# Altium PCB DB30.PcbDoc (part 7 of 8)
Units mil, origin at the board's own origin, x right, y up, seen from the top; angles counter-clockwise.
Board outline 3236.22 x 4456.69 mil, 8 copper layers (Top Layer, MidLayer1, MidLayer2, GND-Layer5, MidLayer3, VCC, MidLayer4, Bottom Layer), stack 61.8 mil thick; 219 components, 472 nets, 1811 pads, 1561 vias.
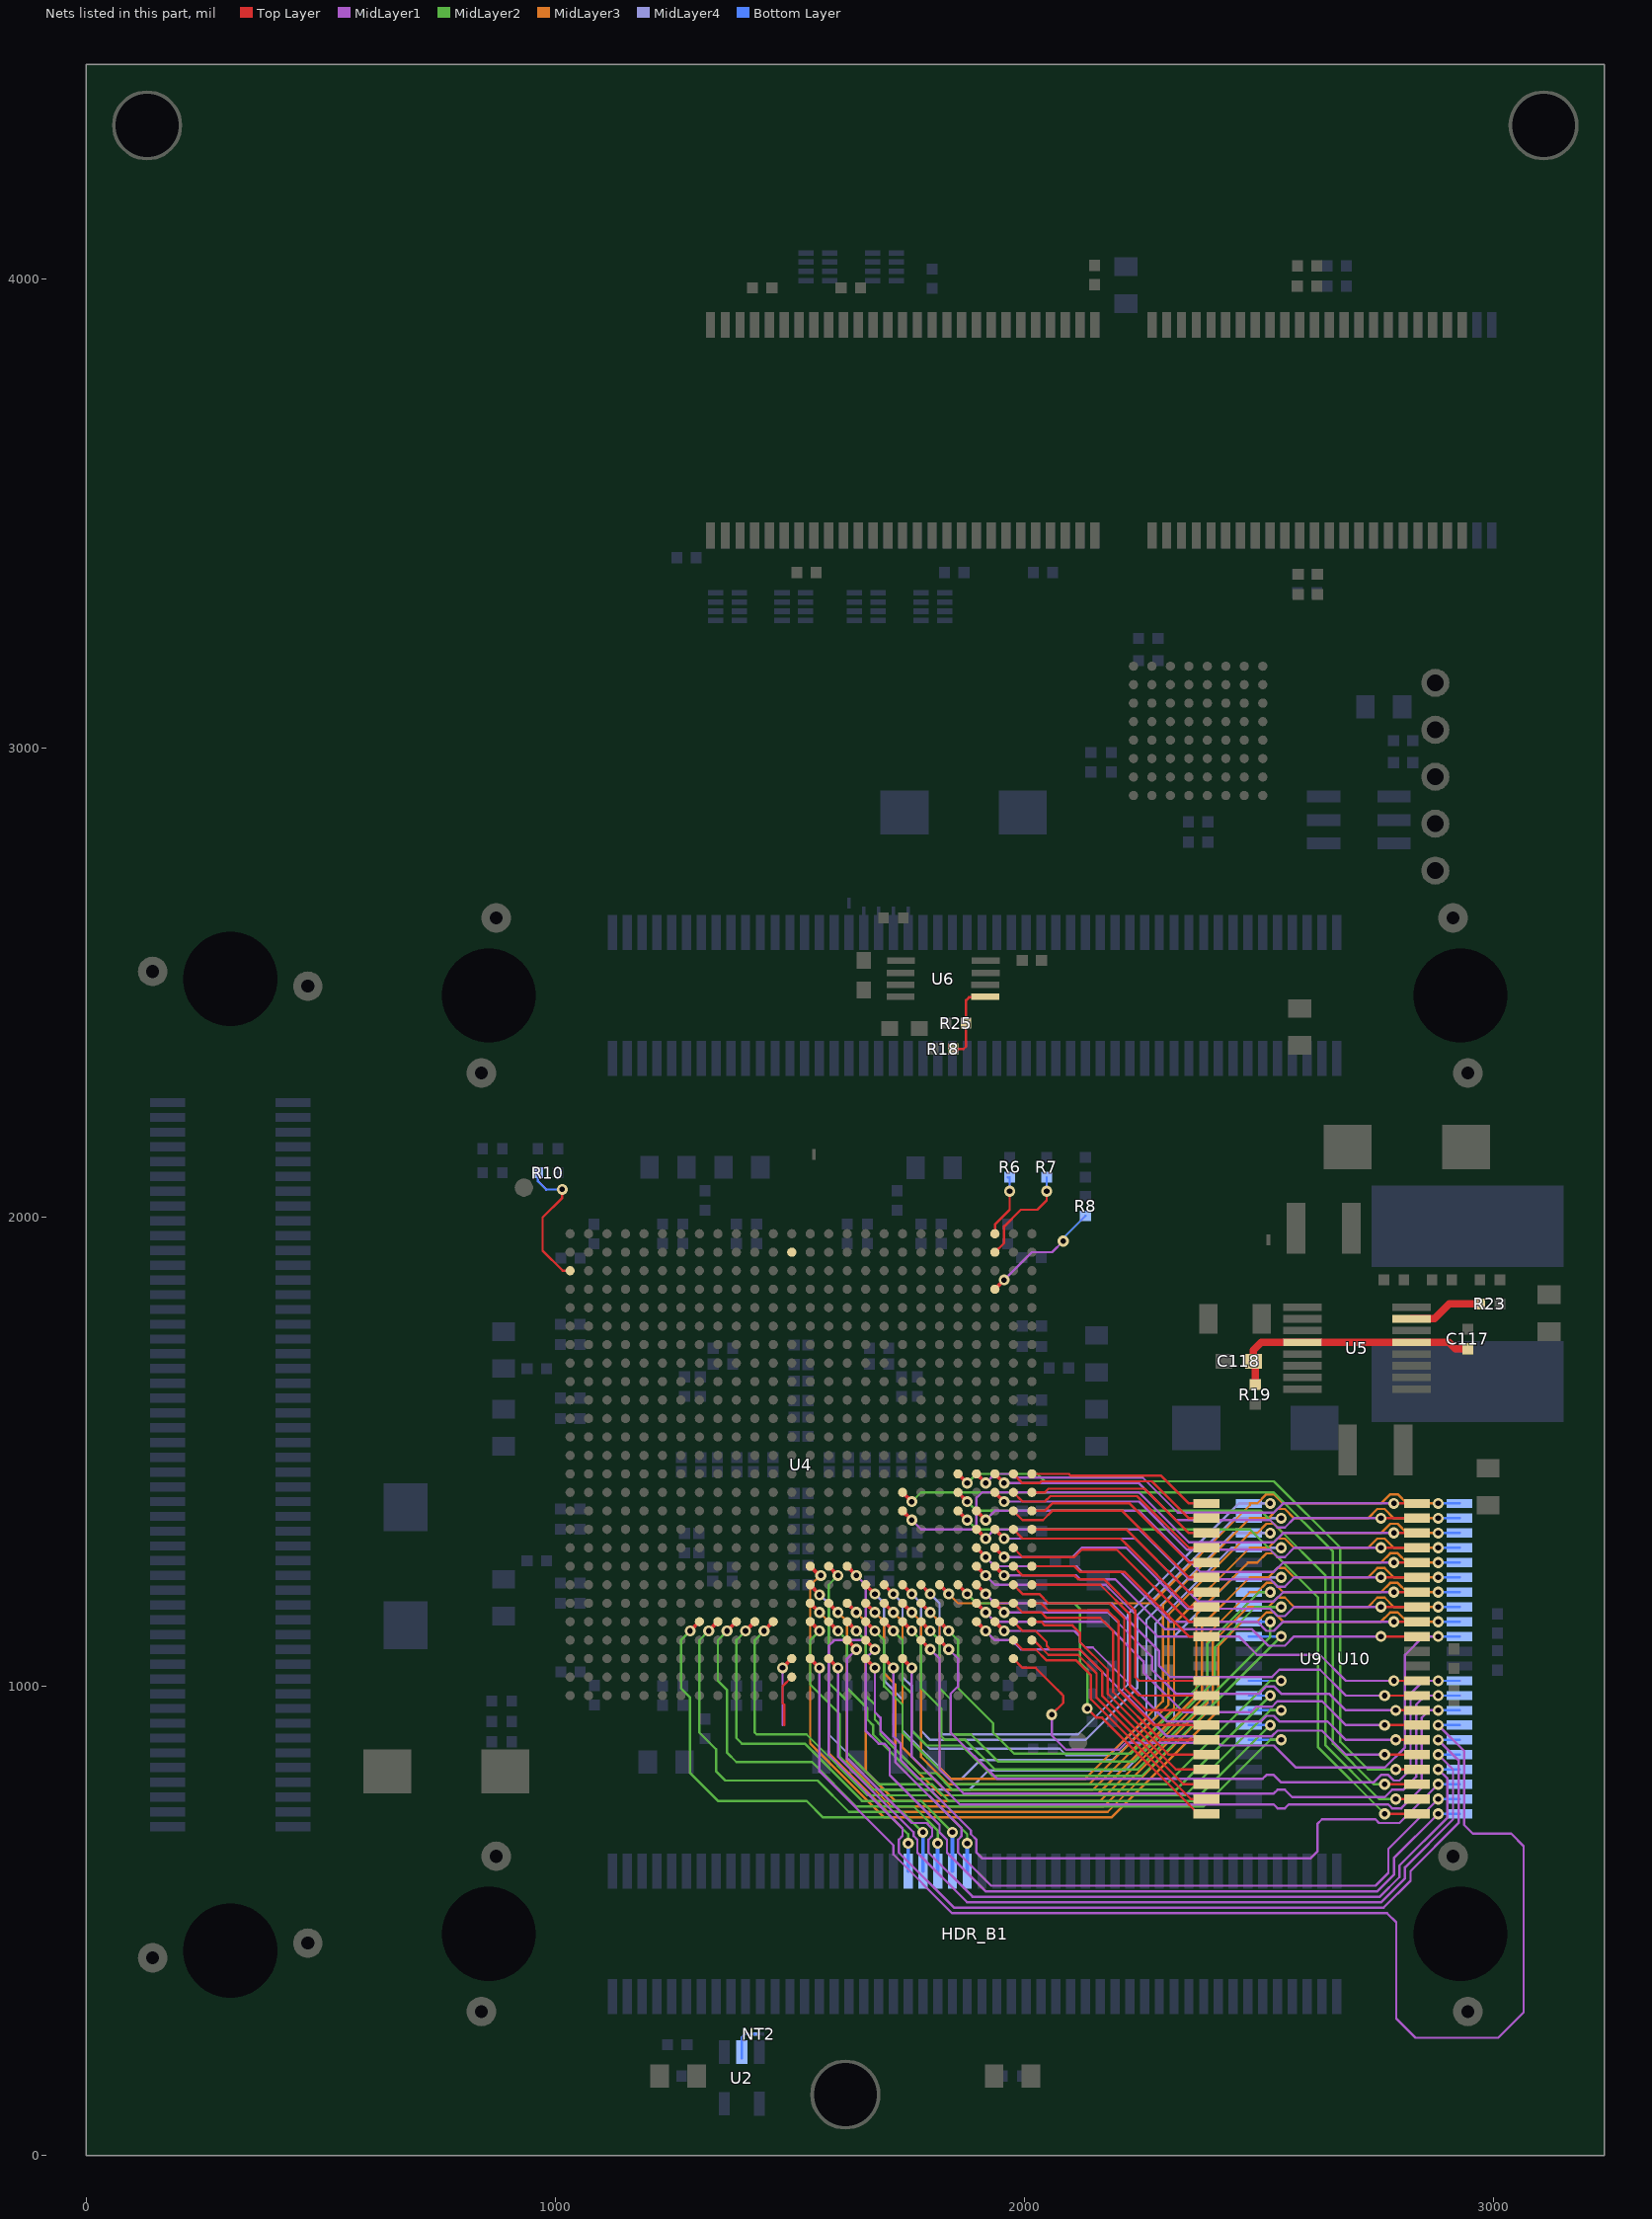
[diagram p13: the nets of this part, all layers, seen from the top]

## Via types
v1: diameter 23.62, hole 11.81, Top Layer to Bottom Layer, 944 vias
v2: diameter 23.62, hole 11.81, Top Layer to Bottom Layer, tented both sides, 477 vias
v3: diameter 27.56, hole 15.75, Top Layer to Bottom Layer, 139 vias
v4: diameter 23.62, hole 11.81, Top Layer to Bottom Layer, tented top, 1 vias

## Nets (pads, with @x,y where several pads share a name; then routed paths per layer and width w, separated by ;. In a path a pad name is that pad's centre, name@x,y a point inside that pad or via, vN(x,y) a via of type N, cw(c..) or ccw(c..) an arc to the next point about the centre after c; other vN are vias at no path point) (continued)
SRAM1_A6: U4.Y17 U10.19 | length 1586.2
  Top Layer w7.87: U4.Y17@1661.42,1216.54 v1(1681.1,1196.85)
  MidLayer4 w5: v1(1681.1,1196.85) 1700.79,1177.16 1700.79,1011.81 1740.16,972.44 1740.16,917.32 1740.16,905.51 1842.52,803.15 1866.14,803.15 1905.51,842.52 2187.01,842.52 2279.53,935.04 2279.53,1133.86 2440.94,1295.28 v1(2547.24,1295.28)
  Bottom Layer w5: U10.19@2478.44,1295.27 v1(2547.24,1295.28) v1@2551.18,1295.28
SRAM1_A7: U4.Y18 U10.20 | length 1489.3
  Top Layer w7.87: U4.Y18@1700.79,1216.54 v1(1720.47,1196.85)
  MidLayer4 w5: v1(1720.47,1196.85) 1740.16,1177.16 1740.16,1019.69 1759.84,1000 1759.84,917.32 1759.84,905.51 1798.23,867.13 2075.05,867.13 2088.83,853.35 2181.1,853.35 2259.84,932.09 2259.84,1141.73 2444.88,1326.77 2456.69,1326.77 v1(2523.83,1326.76)
  Bottom Layer w5: U10.20@2478.44,1326.76 v1@2527.77,1326.76
SRAM1_A8: U4.Y19 U10.21 | length 1468.5
  Top Layer w7.87: U4.Y19@1740.16,1216.54 v1(1759.84,1196.85)
  MidLayer4 w5: v1(1759.84,1196.85) 1779.53,1177.16 1779.53,917.32 1779.53,905.51 1799.21,885.83 2129.92,885.83 2240.16,996.06 2240.16,1151.21 2447.21,1358.27 v1(2547.24,1358.27)
  Bottom Layer w5: U10.21@2472.44,1358.27 U10.21@2478.44,1358.26 v1(2547.24,1358.27) v1@2551.18,1358.27
SRAM1_A9: U4.Y20 U10.22 | length 1372.4
  Top Layer w7.87: U4.Y20@1779.53,1216.54 v1(1799.21,1196.85)
  MidLayer4 w5: v1(1799.21,1196.85) 1818.9,1177.16 1818.9,917.32 1818.9,905.51 1826.77,897.64 2114.17,897.64 2220.47,1003.94 2220.47,1153.54 2456.68,1389.75 v1(2523.83,1389.75)
  Bottom Layer w5: U10.22@2478.44,1389.75 v1(2523.83,1389.75)
SRAM1_A10: U4.Y21 U10.23 | length 1247.9
  Top Layer w7.87: U4.Y21@1818.9,1216.54 v1(1838.58,1196.85)
  MidLayer3 w5: v1(1838.58,1196.85) 1858.27,1177.16 2078.74,1177.17 2094.49,1177.17 2271.65,1177.17 2480.33,1385.84 2480.33,1389.75 2496.27,1389.75 2515.96,1409.44 2531.7,1409.44 2551.38,1389.76 ; 2551.18,1389.76 2551.38,1389.76 ; v1(2881.9,1389.75) 2814.97,1389.75 2795.28,1409.45 2779.53,1409.45 2759.84,1389.76 2551.38,1389.76
  Bottom Layer w5: v1(2881.9,1389.75) U10.23@2927.25,1389.75
SRAM1_A11: U4.AA20 U10.24 | length 1867.3
  Top Layer w7.87: U4.AA20@1779.53,1177.17 v1(1799.21,1157.48)
  MidLayer3 w5: v1(1799.21,1157.48) 1818.9,1137.79 1818.9,917.32 1818.9,905.51 1818.9,826.77 1842.52,803.15 2129.92,803.15 2295.28,968.5 2295.28,1173.23 2480.31,1358.27 2519.69,1358.27 2539.37,1377.95 2555.12,1377.95 2574.8,1358.27 2732.28,1358.27 2751.97,1377.95 2767.72,1377.95 2787.41,1358.26 v1(2881.9,1358.26)
  Bottom Layer w5: v1(2881.9,1358.26) U10.24@2927.25,1358.26
SRAM1_A12: U4.AA19 U10.25 | length 1883.2
  Top Layer w7.87: U4.AA19@1740.16,1177.17 v1(1759.84,1157.48)
  MidLayer3 w5: v1(1759.84,1157.48) 1779.53,1137.79 1779.53,917.32 1779.53,905.51 1779.53,849.41 1837.6,791.34 2137.8,791.34 2307.09,960.63 2307.09,1153.52 2480.33,1326.76 2496.27,1326.76 2515.96,1346.45 2531.7,1346.45 2551.38,1326.77 2759.84,1326.77 2779.53,1346.46 2795.28,1346.46 2814.97,1326.76 v1(2881.9,1326.76)
  Bottom Layer w5: v1(2881.9,1326.76) U10.25@2927.25,1326.76
SRAM1_A13: U4.AA18 U10.26 | length 1900.3
  Top Layer w7.87: U4.AA18@1700.79,1177.17 v1(1720.47,1157.48)
  MidLayer3 w5: v1(1720.47,1157.48) 1740.16,1137.79 1740.16,917.32 1740.16,905.51 1740.16,870.08 1830.71,779.53 2145.67,779.53 2318.9,952.76 2318.9,1133.86 2480.31,1295.28 2519.69,1295.28 2539.37,1314.96 2555.12,1314.96 2574.8,1295.28 2732.28,1295.28 2751.97,1314.96 2767.72,1314.96 2787.41,1295.27 v1(2881.9,1295.27)
  Bottom Layer w5: v1(2881.9,1295.27) U10.26@2927.25,1295.27
SRAM1_A14: U4.AA17 U10.27 | length 1920.3
  Top Layer w7.87: U4.AA17@1661.42,1177.17 v1(1681.1,1157.48)
  MidLayer3 w5: v1(1681.1,1157.48) 1700.79,1137.79 1700.79,1027.56 1724.41,1003.94 1724.41,917.32 1724.41,905.51 1724.41,866.14 1822.83,767.72 2153.54,767.72 2366.14,980.31 2366.14,1153.54 2476.37,1263.77 2496.27,1263.77 2515.96,1283.45 2531.7,1283.45 2551.38,1263.78 2759.84,1263.78 2779.53,1283.46 2795.28,1283.46 2814.97,1263.77 v1(2881.9,1263.77)
  Bottom Layer w5: v1(2881.9,1263.77) U10.27@2927.25,1263.77
SRAM1_A15: U4.AD18 U10.42 | length 1635.8
  Top Layer w7.87: U4.AD18@1700.79,1059.05 v1(1720.47,1039.37)
  MidLayer1 w5: v1(1720.47,1039.37) 1720.47,917.32 1720.47,905.51 1720.47,893.7 1736.22,877.95 1736.22,842.52 1885.83,692.91 1885.83,685.04 1897.64,673.23 1897.64,645.67 1909.45,633.86 2610.24,633.86 2624.26,647.88 2624.26,706.94 2633.86,716.54 2748.03,716.54 2755.91,708.66 2799.21,708.66 v1(2881.9,791.33)
  Bottom Layer w5: v1(2881.9,791.33) U10.42@2927.25,791.33
SRAM1_A16: U4.AD17 U10.43 | length 1706.2
  Top Layer w7.87: U4.AD17@1661.42,1059.05 v1(1681.1,1039.37)
  MidLayer1 w5: v1(1681.1,1039.37) 1681.1,944.88 1692.91,933.07 1692.91,917.32 1692.91,905.51 1724.41,874.02 1724.41,838.58 1866.14,696.85 1866.14,681.1 1858.27,673.23 1858.27,645.67 1928.89,575.05 2748.28,575.05 2775.59,602.36 2775.59,653.54 v1(2881.9,759.83)
  Bottom Layer w5: v1(2881.9,759.83) U10.43@2927.25,759.83
SRAM1_A17: U4.AC17 U10.44 | length 1763.6
  Top Layer w7.87: U4.AC17@1661.42,1098.43 v1(1681.1,1078.74)
  MidLayer1 w5: v1(1681.1,1078.74) 1661.42,1059.05 1661.42,917.32 1661.42,905.51 1688.98,877.95 1700.79,877.95 1712.6,866.14 1712.6,811.02 1818.9,704.72 1818.9,688.98 1834.65,673.23 1834.65,645.67 1917.08,563.24 2752.21,563.24 2787.4,598.43 2787.4,633.86 v1(2881.9,728.34)
  Bottom Layer w5: v1(2881.9,728.34) U10.44@2927.25,728.34
SRAM1_A18: U4.AA16 U10.28 | length 1988.7
  Top Layer w7.87: U4.AA16@1622.05,1177.17 v1(1641.73,1157.48)
  MidLayer3 w5: v1(1641.73,1157.48) 1661.42,1137.79 1661.42,917.32 1661.42,905.51 1661.42,818.9 1724.41,755.91 2161.42,755.91 2377.95,972.44 2377.95,1129.92 2480.31,1232.28 2519.69,1232.28 2539.37,1251.97 2555.12,1251.97 2574.8,1232.28 2732.28,1232.28 2751.97,1251.97 2767.72,1251.97 2787.41,1232.28 v1(2881.9,1232.27)
  Bottom Layer w5: v1(2881.9,1232.27) U10.28@2927.25,1232.27
SRAM1_D0: U4.W15 U10.7 | length 1490.6
  Top Layer w7.87: U4.W15@1582.68,1255.91 v1(1602.36,1236.22)
  MidLayer2 w5: v1(1602.36,1236.22) 1582.68,1216.54 1582.68,1019.68 1582.68,1007.87 1622.05,968.5 1622.05,917.32 1622.05,905.51 1622.05,858.27 1688.98,791.34 1803.15,791.34 1838.58,755.91 2362.2,755.91 2523.6,917.3 v1(2523.83,917.3)
  Bottom Layer w5: U10.7@2478.44,917.31 v1(2523.83,917.3) v1@2527.77,917.3
SRAM1_D1: U4.AB15 U10.8 | length 1351
  Top Layer w7.87: U4.AB15@1582.68,1137.8 v1(1602.36,1118.11)
  MidLayer2 w5: v1(1602.36,1118.11) 1622.05,1098.42 1622.05,996.06 1665.35,952.76 1665.35,929.13 1677.17,917.32 1677.17,905.51 1677.17,897.64 1771.65,803.15 1807.09,803.15 1834.65,775.59 1842.52,767.72 2342.52,767.72 2523.62,948.82 v1(2547.24,948.82)
  Bottom Layer w5: U10.8@2478.44,948.81 v1(2547.24,948.82) v1@2551.18,948.82
SRAM1_D2: U4.AB16 U10.9 | length 1282.1
  Top Layer w7.87: U4.AB16@1622.05,1137.8 v1(1641.73,1118.11)
  MidLayer2 w5: v1(1641.73,1118.11) 1661.42,1098.42 1661.42,980.32 1681.1,960.63 1681.1,929.13 1692.91,917.32 1692.91,905.51 1692.91,897.64 1775.59,814.96 1811.02,814.96 1846.46,779.53 2323.05,779.53 v1(2523.83,980.31) v1@2523.61,980.31
  Bottom Layer w5: U10.9@2478.44,980.31 v1(2523.83,980.31) v1@2527.77,980.31
SRAM1_D3: U4.AB17 U10.10 | length 1285.7
  Top Layer w7.87: U4.AB17@1661.42,1137.8 v1(1681.1,1118.11)
  MidLayer2 w5: v1(1681.1,1118.11) 1700.79,1098.42 1700.79,1000 1740.16,960.63 1740.16,917.32 1740.16,905.51 1740.16,901.57 1850.39,791.34 2303.15,791.34 2523.62,1011.81 v1(2547.24,1011.81)
  Bottom Layer w5: U10.10@2478.44,1011.8 v1(2547.24,1011.81) v1@2551.18,1011.81
SRAM1_D4: U4.AB18 U10.13 | length 1280
  Top Layer w7.87: U4.AB18@1700.79,1137.8 v1(1720.47,1118.11)
  MidLayer2 w5: v1(1720.47,1118.11) 1740.16,1098.42 1740.16,1003.94 1759.84,984.25 1759.84,917.32 1759.84,905.51 1791.34,874.02 1866.14,874.02 1931.1,809.06 2250,809.06 v1(2547.24,1106.3)
  Bottom Layer w5: U10.13@2478.44,1106.29 v1(2547.24,1106.3) v1@2551.18,1106.3
SRAM1_D5: U4.AB19 U10.14 | length 1207.4
  Top Layer w7.87: U4.AB19@1740.16,1137.8 v1(1759.84,1118.11)
  MidLayer2 w5: v1(1759.84,1118.11) 1779.53,1098.42 1779.53,996.06 1822.83,952.76 1822.83,917.32 1822.83,905.51 1822.83,893.7 1830.71,885.83 1874.02,885.83 1937.01,822.83 2241.14,822.83 2523.83,1105.52 v1(2523.83,1137.79)
  Bottom Layer w5: U10.14@2478.44,1137.79 v1@2527.77,1137.79
SRAM1_D6: U4.AB20 U10.15 | length 1243.6
  Top Layer w7.87: U4.AB20@1779.53,1137.8 v1(1799.21,1118.11)
  MidLayer2 w5: v1(1799.21,1118.11) 1818.9,1098.42 1818.9,996.06 1842.52,972.44 1842.52,917.32 1842.52,905.51 1842.52,901.57 1846.46,897.64 1885.83,897.64 1905.51,877.95 1943.9,839.57 2233.27,839.57 2405.51,1011.81 2405.51,1082.68 2492.13,1169.29 v1(2547.24,1169.29)
  Bottom Layer w5: U10.15@2478.44,1169.28 v1(2547.24,1169.29) v1@2551.18,1169.29
SRAM1_D7: U4.AB21 U10.16 | length 1126.6
  Top Layer w7.87: U4.AB21@1818.9,1137.8 v1(1838.58,1118.11)
  MidLayer2 w5: v1(1838.58,1118.11) 1858.27,1098.42 1858.27,996.06 1933.07,921.26 1933.07,917.32 1933.07,905.51 1933.07,901.57 1978.35,856.3 2226.38,856.3 2389.76,1019.69 2389.76,1090.55 2500,1200.79 v1@2523.83,1200.79
  Bottom Layer w5: U10.16@2478.44,1200.78 v1@2527.77,1200.78
  other v1: 2523.83,1200.78
SRAM1_D8: U4.AA15 U10.29 | length 2006.3
  Top Layer w7.87: U4.AA15@1582.68,1177.17 v1(1602.36,1157.48)
  MidLayer3 w5: v1(1602.36,1157.48) 1622.05,1137.79 1622.05,917.32 1622.05,905.51 1622.05,838.58 1716.54,744.09 2169.29,744.09 2389.76,964.57 2389.76,1110.24 2480.3,1200.78 2496.27,1200.78 2515.96,1220.46 2531.7,1220.46 2551.38,1200.79 2759.84,1200.79 2779.53,1220.47 2795.28,1220.47 2814.97,1200.78 v1(2881.9,1200.78)
  Bottom Layer w5: v1(2881.9,1200.78) U10.29@2927.25,1200.78
SRAM1_D9: U4.AA14 U10.30 | length 2026.3
  Top Layer w7.87: U4.AA14@1543.31,1177.17 v1(1562.99,1157.48)
  MidLayer3 w5: v1(1562.99,1157.48) 1582.68,1137.79 1582.68,917.32 1582.68,905.51 1582.68,858.27 1708.66,732.28 2177.17,732.28 2401.57,956.69 2401.57,1094.49 2476.38,1169.29 2519.69,1169.29 2539.37,1188.98 2555.12,1188.98 2574.8,1169.29 2732.28,1169.29 2751.97,1188.98 2767.72,1188.98 2787.41,1169.29 v1(2881.9,1169.28)
  Bottom Layer w5: v1(2881.9,1169.28) U10.30@2927.25,1169.28
SRAM1_D10: U4.W14 U10.31 | length 2131.8
  Top Layer w7.87: U4.W14@1543.31,1255.91 v1@1562.99,1236.22
  MidLayer3 w5: v1(1565.94,1236.22) 1543.31,1216.54 1543.31,917.32 1543.31,905.51 1543.31,877.95 1700.79,720.47 2185.04,720.47 2413.39,948.82 2413.39,1086.61 2464.56,1137.79 2496.27,1137.79 2515.96,1157.47 2531.7,1157.47 2551.38,1137.8 2759.84,1137.8 2779.53,1157.48 2795.28,1157.48 2814.97,1137.79 v1(2881.9,1137.79)
  Bottom Layer w5: v1(2881.9,1137.79) U10.31@2927.25,1137.79
SRAM1_D11: U4.AD25 U10.32 | length 1379.1
  Top Layer w5: U4.AD25@1976.38,1059.05 1996.06,1039.37 2023.62,1039.37 2070.87,992.13 2078.74,984.25 2082.68,980.32 2082.68,964.57 v1(2058.07,939.96)
  MidLayer1 w5: v1(2058.07,939.96) 2058.07,895.67 2088.58,865.16 2201.53,865.16 2216.29,879.92 2412.65,879.92 2418.55,874.02 2531.5,874.02 2578.75,826.76 2767.71,826.76 2811.02,870.08 2811.02,1066.93 2850.39,1106.3 2862.59,1106.3 ; 2858.28,1106.29 v1(2881.9,1106.29)
  Bottom Layer w5: v1(2881.9,1106.29) U10.32@2927.25,1106.29
SRAM1_D12: U4.AC21 U10.35 | length 1549
  Top Layer w7.87: U4.AC21@1818.9,1098.43 v1(1838.58,1078.74)
  MidLayer1 w5: v1(1838.58,1078.74) 1858.27,1059.05 1858.27,1000 1842.52,984.25 1842.52,917.32 1842.52,905.51 1842.52,901.57 1940.94,803.15 2507.87,803.15 2515.75,811.02 2531.5,811.02 2547.24,795.28 2744.09,795.27 2759.84,811.02 2775.6,811.02 2787.4,799.21 2799.21,799.21 2822.83,822.83 2822.83,984.25 2850.39,1011.81 2862.2,1011.81 ; 2862.21,1011.8 v1(2881.9,1011.8)
  Bottom Layer w5: v1(2881.9,1011.8) U10.35@2927.25,1011.8
SRAM1_D13: U4.AC20 U10.36 | length 1610.9
  Top Layer w7.87: U4.AC20@1779.53,1098.43 v1(1799.21,1078.74)
  MidLayer1 w5: v1(1799.21,1078.74) 1818.9,1059.05 1818.9,917.32 1818.9,905.51 1818.9,822.83 1870.08,771.65 2531.5,771.65 2539.37,779.53 2555.12,779.53 2570.87,763.78 2767.71,763.77 2783.46,779.52 2807.08,779.52 2834.65,807.09 2834.65,960.63 2854.33,980.32 2862.2,980.32 v1(2881.9,980.31)
  Bottom Layer w5: v1(2881.9,980.31) U10.36@2927.25,980.31
SRAM1_D14: U4.AD19 U10.37 | length 1610.5
  Top Layer w7.87: U4.AD19@1740.16,1059.05 v1(1759.84,1039.37)
  MidLayer1 w5: v1(1759.84,1039.37) 1759.84,917.32 1759.84,905.51 1759.84,850.39 1862.2,748.03 2531.5,748.03 2539.37,740.16 2555.12,740.16 2562.99,748.03 2775.59,748.03 2783.46,740.16 2803.15,740.16 2846.46,783.46 2846.46,933.07 2862.2,948.82 v1(2881.9,948.81)
  Bottom Layer w5: v1(2881.9,948.81) U10.37@2927.25,948.81
SRAM1_D15: U4.AD14 U10.38 | length 2919.2
  Top Layer w7.87: U4.AD14@1543.31,1059.05 v1(1562.99,1039.37)
  MidLayer1 w5: v1(1562.99,1039.37) 1562.99,917.32 1562.99,905.51 1562.99,818.9 1720.47,661.42 1720.47,641.73 1845.47,516.73 2772.64,516.73 2792.32,497.05 2792.32,292.32 2833.66,250.98 3009.84,250.98 3063.98,305.12 3063.98,659.45 3037.4,686.02 2955.71,686.02 2937.01,704.72 2937.01,862.2 v1(2881.9,917.31)
  Bottom Layer w5: v1(2881.9,917.31) U10.38@2927.25,917.31
SRAM1_NBHE: U4.AD15 U10.40 | length 1960.2
  Top Layer w7.87: U4.AD15@1582.68,1059.05 v1(1602.36,1039.37)
  MidLayer1 w5: v1(1602.36,1039.37) 1602.36,917.32 1602.36,905.51 1602.36,850.39 1763.78,688.98 1763.78,681.1 1771.65,673.23 1771.65,645.67 1877.21,540.11 2760.58,540.11 2811.02,590.55 2811.02,614.17 2913.39,716.54 2913.39,822.83 v1(2881.9,854.32)
  Bottom Layer w5: v1(2881.9,854.32) U10.40@2927.25,854.32
SRAM1_NBLE: U4.W16 U10.39 | length 2330.8
  Top Layer w7.87: U4.W16@1622.05,1255.91 v1(1641.73,1236.22)
  MidLayer1 w5: v1(1641.73,1236.22) 1661.42,1216.53 1661.42,1106.3 1653.54,1098.43 1594.49,1098.43 1582.68,1086.61 1582.68,952.76 1582.68,917.32 1582.68,905.51 1582.68,854.33 1740.16,696.85 1740.16,681.1 1732.28,673.23 1732.28,645.67 1849.41,528.54 2765.75,528.54 2822.83,585.63 2822.83,606.3 2925.2,708.66 2925.2,842.52 v1(2881.9,885.82)
  Bottom Layer w5: v1(2881.9,885.82) U10.39@2927.25,885.82
SRAM1_NCS: U4.AB14 U10.6 | length 1446.2
  Top Layer w7.87: U4.AB14@1543.31,1137.8 v1(1562.99,1118.11)
  MidLayer2 w5: v1(1562.99,1118.11) 1543.31,1098.42 1543.31,1003.94 1606.3,940.94 1606.3,917.32 1606.3,905.51 1606.3,850.39 1677.17,779.53 1799.21,779.53 1834.65,744.09 2381.89,744.09 2523.62,885.83 v1(2547.24,885.83)
  Bottom Layer w5: U10.6@2478.44,885.82 v1(2547.24,885.83) v1@2551.18,885.83
SRAM1_NOE: U4.AC16 U10.41 | length 1951.2
  Top Layer w7.87: U4.AC16@1622.05,1098.43 v1(1641.73,1078.74)
  MidLayer1 w5: v1(1641.73,1078.74) 1622.05,1059.05 1622.05,917.32 1622.05,905.51 1622.05,846.46 1759.84,708.66 1791.34,708.66 1799.21,700.79 1803.15,696.85 1803.15,681.1 1795.28,673.23 1795.28,645.67 1889.27,551.67 2757.38,551.67 2799.21,593.5 2799.21,618.11 2901.57,720.47 2901.57,803.15 v1(2881.9,822.83)
  Bottom Layer w5: v1(2881.9,822.83) U10.41@2927.25,822.83
SRAM1_NWE: U4.Y14 U10.17 | length 1715.1
  Top Layer w7.87: U4.Y14@1543.31,1216.54 v1(1562.99,1194.88)
  MidLayer4 w5: v1(1562.99,1194.88) 1582.68,1177.16 1582.68,917.32 1582.68,905.51 1582.68,897.64 1700.79,779.53 1881.89,779.53 1923.23,820.87 2214.57,820.87 2318.9,925.2 2318.9,1106.3 2444.88,1232.28 v1(2547.24,1232.28)
  Bottom Layer w5: U10.17@2478.44,1232.28 v1(2547.24,1232.28) v1@2551.18,1232.28
SRAM2_A0: U4.T22 U9.1 | length 1432.7
  Top Layer w5: v1(2767.69,728.34) U9.1@2836.71,728.34
  Top Layer w7.87: U4.T22@1858.27,1374.02 v1(1877.95,1354.33)
  MidLayer2 w5: v1(1877.95,1354.33) 1897.64,1334.65 2078.74,1334.65 2094.49,1334.65 2480.31,1334.65 2625.98,1188.98 2625.98,870.08 v1(2767.69,728.34)
SRAM2_A1: U4.R22 U9.2 | length 1461.3
  Top Layer w5: v1(2791.34,759.84) U9.2@2836.71,759.83
  Top Layer w7.87: U4.R22@1858.27,1413.39 v1(1877.95,1393.7)
  MidLayer2 w5: v1(1877.95,1393.7) 1897.64,1374.02 2078.74,1374.02 2094.49,1374.02 2503.94,1374.02 2539.37,1338.58 2641.73,1236.22 2641.73,874.02 2755.91,759.84 v1(2791.34,759.84)
SRAM2_A2: U4.R19 U9.3 | length 1610.4
  Top Layer w5: v1(2767.69,791.34) U9.3@2836.71,791.33
  Top Layer w7.87: U4.R19@1740.16,1413.39 v1(1759.84,1393.7)
  MidLayer2 w5: v1(1759.84,1393.7) 1779.53,1413.38 2078.74,1413.39 2094.49,1413.39 2531.5,1413.39 2657.48,1287.4 2657.48,877.95 2744.1,791.34 v1(2767.69,791.34)
SRAM2_A3: U4.P22 U9.4 | length 1497.8
  Top Layer w5: v1(2791.34,822.83) U9.4@2836.71,822.83
  Top Layer w7.87: U4.P22@1858.27,1452.76 v1(1877.95,1433.07)
  MidLayer2 w5: v1(1877.95,1433.07) 1897.64,1452.76 2027.56,1452.76 2043.31,1437.01 2078.74,1437.01 2094.49,1437.01 2531.5,1437.01 2673.23,1295.28 2673.23,881.89 2732.28,822.83 v1(2791.34,822.83)
SRAM2_A4: U4.AB23 U9.5 | length 1058.4
  Top Layer w5: v1(2767.69,854.33) U9.5@2836.71,854.32
  Top Layer w7.87: U4.AB23@1897.64,1137.8 v1(1917.32,1118.11)
  MidLayer1 w5: v1(1917.32,1118.11) 1937.01,1098.43 1972.44,1098.43 1992.13,1078.74 2078.74,1078.74 2094.49,1078.74 2118.11,1078.74 2303.15,893.7 2527.56,893.7 2539.37,905.51 2633.86,905.51 2685.04,854.33 v1@2759.84,854.31
SRAM2_A5: U4.T23 U9.18 | length 1017.4
  Top Layer w5: v1@2787.4,1263.77 U9.18@2836.71,1263.77
  Top Layer w7.87: U4.T23@1897.64,1374.02 v1(1917.32,1354.33)
  MidLayer1 w5: v1(1917.32,1354.33) 1937.01,1374.01 2078.74,1374.01 2094.49,1374.02 2244.09,1374.02 2374.02,1244.09 2531.5,1244.09 2551.18,1263.78 v1(2787.4,1263.78)
SRAM2_A6: U4.R24 U9.19 | length 964.9
  Top Layer w5: v1(2759.84,1295.28) U9.19@2836.71,1295.27
  Top Layer w7.87: U4.R24@1937.01,1413.39 v1(1956.69,1393.7)
  MidLayer1 w5: v1(1956.69,1393.7) 2078.74,1393.7 2094.49,1393.7 2244.09,1393.7 2346.46,1291.34 2523.62,1291.34 2539.37,1275.59 2555.12,1275.59 2574.8,1295.28 v1(2759.84,1295.28)
SRAM2_A7: U4.T19 U9.20 | length 1232.3
  Top Layer w5: v1(2787.4,1326.77) U9.20@2836.71,1326.76
  Top Layer w7.87: U4.T19@1740.16,1374.02 v1(1759.84,1354.33)
  MidLayer1 w5: v1(1759.84,1354.33) 1779.53,1334.65 1889.76,1334.65 1897.64,1342.52 1897.64,1401.57 1909.45,1413.39 2043.31,1413.39 2078.74,1413.39 2094.49,1413.39 2244.09,1413.39 2350.39,1307.09 2531.5,1307.09 2551.18,1326.77 v1(2787.4,1326.77)
SRAM2_A8: U4.P24 U9.21 | length 955.1
  Top Layer w5: v1(2759.84,1358.27) U9.21@2836.71,1358.26
  Top Layer w7.87: U4.P24@1937.01,1452.76 v1(1956.69,1433.07)
  MidLayer1 w5: v1(1956.69,1433.07) 2078.74,1433.07 2094.49,1433.07 2244.09,1433.07 2322.83,1354.33 2523.62,1354.33 2539.37,1338.58 2555.12,1338.58 2574.8,1358.27 v1(2759.84,1358.27)
SRAM2_A9: U4.P23 U9.22 | length 997.8
  Top Layer w5: v1(2787.4,1389.76) U9.22@2836.71,1389.76
  Top Layer w7.87: U4.P23@1897.64,1452.76 v1(1917.32,1433.07)
  MidLayer1 w5: v1(1917.32,1433.07) 1937.01,1452.76 1968.5,1452.76 1976.38,1444.88 2078.74,1444.88 2094.49,1444.88 2251.97,1444.88 2326.77,1370.08 2531.5,1370.08 2551.18,1389.76 v1(2787.4,1389.76)
SRAM2_A10: U4.P26 U9.23 | length 398.2
  Top Layer w5: U4.P26@2015.75,1452.76 2078.74,1452.76 2094.49,1452.76 2098.43,1448.82 2291.34,1448.82 2350.4,1389.76 U9.23@2387.89,1389.76
SRAM2_A11: U4.P25 U9.24 | length 453.9
  Top Layer w5: U4.P25@1976.38,1452.76 1996.06,1433.07 2031.5,1433.07 2035.43,1437.01 2078.74,1437.01 2094.49,1437.01 2271.65,1437.01 2350.4,1358.26 U9.24@2387.89,1358.26
SRAM2_A12: U4.R26 U9.25 | length 414.5
  Top Layer w5: U4.R26@2015.75,1413.39 2043.31,1413.39 2051.18,1421.26 2078.74,1421.26 2094.49,1421.26 2255.91,1421.26 2350.4,1326.76 U9.25@2387.89,1326.76
SRAM2_A13: U4.R25 U9.26 | length 470.2
  Top Layer w5: U4.R25@1976.38,1413.39 1996.06,1393.7 2043.31,1393.7 2055.12,1405.51 2078.74,1405.51 2094.49,1405.51 2240.16,1405.51 2350.4,1295.27 U9.26@2387.89,1295.27
SRAM2_A14: U4.T26 U9.27 | length 430.9
  Top Layer w5: U4.T26@2015.75,1374.02 2043.31,1374.02 2059.06,1389.76 2078.74,1389.76 2094.49,1389.76 2224.41,1389.76 2350.4,1263.77 U9.27@2387.89,1263.77
SRAM2_A15: U4.AC26 U9.42 | length 529.3
  Top Layer w5: U4.AC26@2015.75,1098.43 2019.69,1098.43 2051.18,1066.93 2078.74,1066.93 2090.55,1066.93 2114.17,1066.93 2153.54,1027.56 2153.54,976.38 2338.59,791.33 U9.42@2387.89,791.33
SRAM2_A16: U4.AC25 U9.43 | length 581.7
  Top Layer w5: U4.AC25@1976.38,1098.43 1996.06,1078.74 2023.62,1078.74 2047.24,1055.12 2078.74,1055.12 2090.55,1055.12 2110.24,1055.12 2141.73,1023.62 2141.73,972.44 2354.34,759.83 U9.43@2387.89,759.83
SRAM2_A17: U4.Y22 U9.44 | length 847.2
  Top Layer w5: v1(2133.86,952.76) 2153.54,933.07 2165.35,933.07 2370.09,728.34 U9.44@2387.89,728.34
  Top Layer w7.87: U4.Y22@1858.27,1216.54 v1(1877.95,1196.85)
  MidLayer2 w5: v1(1877.95,1196.85) 1897.64,1177.17 2078.74,1177.17 2094.49,1177.17 2106.3,1177.17 2118.11,1165.35 2118.11,1051.18 2133.86,1035.43 v1(2133.86,952.76)
SRAM2_A18: U4.T25 U9.28 | length 486.5
  Top Layer w5: U4.T25@1976.38,1374.02 1996.06,1354.33 2039.37,1354.33 2059.05,1374.02 2078.74,1374.02 2094.49,1374.02 2208.66,1374.02 2350.4,1232.28 U9.28@2387.89,1232.28
SRAM2_D0: U4.AA23 U9.7 | length 1072.4
  Top Layer w5: v1(2767.69,917.32) U9.7@2836.71,917.32
  Top Layer w7.87: U4.AA23@1897.64,1177.17 v1(1917.32,1157.48)
  MidLayer1 w5: v1(1917.32,1157.48) 1937.01,1137.8 2078.74,1137.8 2094.49,1137.8 2169.29,1137.8 2253.94,1053.15 2253.94,1029.53 2338.58,944.88 2482.35,944.88 2494.16,956.69 2527.58,956.69 2539.11,968.23 2539.11,968.5 2633.86,968.5 2685.06,917.3 v1@2759.84,917.3
SRAM2_D1: U4.AA24 U9.8 | length 1019.5
  Top Layer w5: v1(2791.34,948.82) U9.8@2836.71,948.81
  Top Layer w7.87: U4.AA24@1937.01,1177.17 v1(1956.69,1157.48)
  MidLayer1 w5: v1(1956.69,1157.48) 2078.74,1157.48 2094.49,1157.48 2177.17,1157.48 2271.65,1062.99 2271.65,1035.43 2322.83,984.25 2500,984.25 2515.75,1000 2531.5,1000 2547.24,984.25 2649.61,984.25 2685.04,948.83 v1@2787.41,948.83
SRAM2_D2: U4.Y23 U9.9 | length 1060.6
  Top Layer w5: v1(2767.69,980.31) U9.9@2836.71,980.31
  Top Layer w7.87: U4.Y23@1897.64,1216.54 v1(1917.32,1196.85)
  MidLayer1 w5: v1(1917.32,1196.85) 1937.01,1177.17 2031.5,1177.17 2078.74,1177.17 2094.49,1177.17 2185.04,1177.17 2286.43,1075.77 2286.43,1044.28 2311.02,1019.68 2527.56,1019.68 2543.31,1035.43 2629.92,1035.43 2685.04,980.32 ; 2685.04,980.29 v1@2759.84,980.29
SRAM2_D3: U4.W23 U9.10 | length 1040.2
  Top Layer w5: v1(2787.4,1011.81) U9.10@2836.71,1011.8
  Top Layer w7.87: U4.W23@1897.64,1255.91 v1(1917.32,1236.22)
  MidLayer1 w5: v1(1917.32,1236.22) 1937.01,1216.54 2078.74,1216.54 2094.49,1216.54 2173.23,1216.54 2283.46,1106.3 2456.69,1106.3 2496.06,1066.93 2629.92,1066.93 2685.03,1011.82 v1(2787.4,1011.81)
SRAM2_D4: U4.W24 U9.13 | length 978
  Top Layer w5: v1(2759.84,1106.3) U9.13@2836.71,1106.29
  Top Layer w7.87: U4.W24@1937.01,1255.91 v1(1956.69,1236.22)
  MidLayer1 w5: v1(1956.69,1236.22) 2078.74,1236.22 2094.49,1236.22 2110.24,1236.22 2118.11,1228.35 2192.91,1228.35 2299.21,1122.05 2484.25,1122.05 2519.68,1086.62 2555.11,1086.62 2574.79,1106.31 v1(2759.84,1106.3)
SRAM2_D5: U4.V23 U9.14 | length 1020.6
  Top Layer w5: v1(2787.4,1137.8) U9.14@2836.71,1137.79
  Top Layer w7.87: U4.V23@1897.64,1295.28 v1(1917.32,1275.59)
  MidLayer1 w5: v1(1917.32,1275.59) 1937.01,1255.91 2078.74,1255.91 2094.49,1255.91 2110.24,1255.91 2122.05,1244.09 2204.72,1244.09 2311.02,1137.8 2496.06,1137.8 2515.75,1118.11 2531.49,1118.11 2551.17,1137.8 ; 2551.17,1137.8 v1(2787.4,1137.8)
SRAM2_D6: U4.V24 U9.15 | length 984.5
  Top Layer w5: v1(2759.84,1169.29) U9.15@2836.71,1169.28
  Top Layer w7.87: U4.V24@1937.01,1295.28 v1(1956.69,1275.59)
  MidLayer1 w5: v1(1956.69,1275.59) 2078.74,1275.59 2094.49,1275.59 2102.36,1275.59 2122.05,1295.28 2216.54,1295.28 2346.45,1165.36 2523.61,1165.36 2539.36,1149.61 2555.11,1149.61 2574.79,1169.3 v1(2759.84,1169.29)
SRAM2_D7: U4.U24 U9.16 | length 971.4
  Top Layer w5: v1(2787.4,1200.79) U9.16@2836.71,1200.78
  Top Layer w7.87: U4.U24@1937.01,1334.65 v1(1956.69,1314.96)
  MidLayer1 w5: v1(1956.69,1314.96) 2078.74,1314.96 2094.49,1314.96 2236.22,1314.96 2370.08,1181.1 2531.49,1181.1 ; 2531.49,1181.11 2551.17,1200.8 ; 2551.17,1200.8 v1(2787.4,1200.79)
SRAM2_D8: U4.U26 U9.29 | length 427.6
  Top Layer w5: U4.U26@2015.75,1334.65 2078.74,1334.65 2094.49,1334.65 2216.54,1334.65 2350.4,1200.78 U9.29@2387.89,1200.78
SRAM2_D9: U4.U25 U9.30 | length 480
  Top Layer w5: U4.U25@1976.38,1334.65 1996.06,1314.96 2078.74,1314.96 2094.49,1314.96 2204.72,1314.96 2216.54,1303.15 2350.4,1169.28 U9.30@2387.89,1169.28
SRAM2_D10: U4.V25 U9.31 | length 489.8
  Top Layer w5: U4.V25@1976.38,1295.28 1996.06,1275.59 2078.74,1275.59 2094.49,1275.59 2106.3,1275.59 2122.05,1291.34 2196.85,1291.34 2350.4,1137.79 U9.31@2387.89,1137.79
SRAM2_D11: U4.W26 U9.32 | length 434.1
  Top Layer w5: U4.W26@2015.75,1255.91 2078.74,1255.91 2094.49,1255.91 2106.3,1255.91 2118.11,1244.09 2212.6,1244.09 2350.4,1106.29 U9.32@2387.89,1106.29
SRAM2_D12: U4.W25 U9.35 | length 595.6
  Top Layer w5: U4.W25@1976.38,1255.91 1996.06,1236.22 2078.74,1236.22 2094.49,1236.22 2106.3,1236.22 2114.17,1228.35 2169.29,1228.35 2236.22,1161.42 2236.22,1019.68 2244.1,1011.8 U9.35@2387.89,1011.8
SRAM2_D13: U4.Y26 U9.36 | length 559.9
  Top Layer w5: U4.Y26@2015.75,1216.54 2078.74,1216.54 2094.49,1216.54 2161.42,1216.54 2224.41,1153.54 2224.41,1000 2244.1,980.31 U9.36@2387.89,980.31
SRAM2_D14: U4.Y25 U9.37 | length 610
  Top Layer w5: U4.Y25@1976.38,1216.54 1996.06,1196.85 2031.5,1196.85 2051.18,1177.17 2078.74,1177.17 2094.49,1177.17 2181.1,1177.17 2212.6,1145.67 2212.6,996.06 2259.85,948.81 U9.37@2387.89,948.81
SRAM2_D15: U4.AA26 U9.38 | length 565.1
  Top Layer w5: U4.AA26@2015.75,1177.17 2035.43,1177.17 2051.18,1161.42 2078.74,1161.42 2094.49,1161.42 2177.17,1161.42 2200.79,1137.8 2200.79,992.13 2275.6,917.32 U9.38@2387.89,917.32
SRAM2_NBHE: U4.AB26 U9.40 | length 531.1
  Top Layer w5: U4.AB26@2015.75,1137.8 2035.43,1137.8 2043.31,1129.92 2078.74,1129.92 2094.49,1129.92 2102.36,1129.92 2118.11,1114.17 2118.11,1094.49 2177.17,1035.43 2177.17,984.25 2307.09,854.32 U9.40@2387.89,854.32
SRAM2_NBLE: U4.AA25 U9.39 | length 608.3
  Top Layer w5: U4.AA25@1976.38,1177.17 1996.06,1157.48 2000,1157.48 2031.5,1157.48 2035.43,1157.48 2047.24,1145.67 2078.74,1145.67 2094.49,1145.67 2161.42,1145.67 2188.98,1118.11 2188.98,988.19 2291.35,885.82 U9.39@2387.89,885.82
SRAM2_NCS: U4.AB24 U9.6 | length 1016.8
  Top Layer w5: v1(2791.34,885.83) U9.6@2836.71,885.82
  Top Layer w7.87: U4.AB24@1937.01,1137.8 v1(1956.69,1118.11)
  MidLayer1 w5: v1(1956.69,1118.11) 2078.74,1118.11 2094.49,1118.11 2106.3,1118.11 2118.11,1106.3 2118.11,1094.49 2129.92,1082.68 2145.67,1082.68 2303.15,925.2 2503.93,925.2 2515.75,937.01 2531.5,937.01 2543.31,925.2 2645.67,925.2 2685.03,885.83 v1@2787.41,885.83
SRAM2_NOE: U4.AB25 U9.41 | length 576.6
  Top Layer w5: U4.AB25@1976.38,1137.8 1996.06,1118.11 2023.62,1118.11 2047.24,1094.49 2047.24,1086.61 2055.12,1078.74 2078.74,1078.74 2090.55,1078.74 2118.11,1078.74 2165.35,1031.5 2165.35,980.32 2322.84,822.83 U9.41@2387.89,822.83
SRAM2_NWE: U4.U23 U9.17 | length 1014.1
  Top Layer w5: v1(2759.84,1232.28) U9.17@2836.71,1232.28
  Top Layer w7.87: U4.U23@1897.64,1334.65 v1(1917.32,1314.96)
  MidLayer1 w5: v1(1917.32,1314.96) 1937.01,1334.64 2051.18,1334.64 2078.74,1334.65 2094.49,1334.65 2244.09,1334.65 2350.39,1228.35 2523.61,1228.35 2539.36,1212.61 2555.11,1212.61 2574.79,1232.29 v1(2759.84,1232.28)
STATUS_LED: NT2.1 U2.2 | length 74.7
  Bottom Layer w5: U2.2@1397.64,207.68 U2.2@1397.64,220.47 1397.64,251.97 1404.53,258.86 NT2.1@1425.2,258.86
SW0: HDR_B1.42 U4.AB8 | length 944.4
  Top Layer w7.87: v1(1287.4,1118.11) U4.AB8@1307.09,1137.8
  MidLayer2 w5: v1(1287.4,1118.11) 1267.72,1098.42 1267.72,996.06 1287.4,976.38 1287.4,917.32 1287.4,905.51 1287.4,814.96 1346.46,755.91 1535.43,755.91 1570.87,720.47 1716.54,720.47 1751.97,685.04 v2(1751.97,665.35)
  Bottom Layer w7.87: HDR_B1.42@1751.97,606.3 v2(1751.97,665.35)
SW1: HDR_B1.44 U4.AB9 | length 927.3
  Top Layer w7.87: v1(1326.77,1118.11) U4.AB9@1346.46,1137.8
  MidLayer2 w5: v1(1326.77,1118.11) 1307.09,1098.42 1307.09,917.32 1307.09,905.51 1307.09,901.57 1342.52,866.14 1342.52,818.9 1362.2,799.21 1559.06,799.21 1625.98,732.28 1740.16,732.28 v2(1783.46,688.98)
  Bottom Layer w7.87: HDR_B1.44@1783.47,606.3 v2(1783.46,688.98)
SW2: HDR_B1.46 U4.AB10 | length 907.9
  Top Layer w7.87: v1(1366.14,1118.11) U4.AB10@1385.83,1137.8
  MidLayer2 w5: v1(1366.14,1118.11) 1346.46,1098.42 1346.46,1011.81 1366.14,992.13 1366.14,917.32 1366.14,905.51 1366.14,858.27 1385.83,838.58 1547.24,838.58 1641.73,744.09 1763.78,744.09 1814.96,692.91 v2(1814.96,665.35)
  Bottom Layer w7.87: HDR_B1.46@1814.96,606.3 v2(1814.96,665.35)
SW3: HDR_B1.48 U4.AB11 | length 890.8
  Top Layer w7.87: v1(1405.51,1118.11) U4.AB11@1425.2,1137.8
  MidLayer2 w5: v1(1405.51,1118.11) 1385.83,1098.42 1385.83,917.32 1385.83,905.51 1385.83,889.76 1397.64,877.95 1531.5,877.95 1653.54,755.91 1779.53,755.91 v2(1846.46,688.98)
  Bottom Layer w7.87: HDR_B1.48@1846.46,606.3 v2(1846.46,688.98)
SW4: HDR_B1.50 U4.AB12 | length 873.7
  Top Layer w7.87: v1(1444.88,1118.11) U4.AB12@1464.57,1137.8
  MidLayer2 w5: v1(1444.88,1118.11) 1425.2,1098.42 1425.2,917.32 1425.2,905.51 1425.2,901.57 1429.13,897.64 1535.43,897.64 1665.35,767.72 1795.28,767.72 1877.95,685.04 v2(1877.95,665.35)
  Bottom Layer w7.87: HDR_B1.50@1877.96,606.3 v2(1877.95,665.35)
TCK: R7.2 U4.B24 | length 226.3
  Top Layer w5: U4.B24@1937.01,1925.2 1956.69,1944.88 1956.69,1980.32 1992.13,2015.75 2027.56,2015.75 2047.24,2035.43 v1(2047.24,2055.12)
  Bottom Layer w5: v1(2047.24,2055.12) R7.2@2047.24,2085.12
TDI: R10.2 U4.C1 | length 301.1
  Top Layer w5: v1(1014.76,2059.06) 1014.76,2041.34 973,1999.57 973,1928.57 1015.75,1885.83 U4.C1@1031.5,1885.83
  Bottom Layer w5: R10.2@963.07,2094.48 963.07,2076.3 980.61,2058.76 v1(1014.76,2059.06)
TDO: R8.2 U4.D24 | length 261.3
  Top Layer w7.87: U4.D24@1937.01,1846.46 v1(1956.69,1866.14)
  MidLayer1 w5: v1(1956.69,1866.14) 2015.75,1925.2 2059.06,1925.2 v1(2082.68,1948.82)
  Bottom Layer w5: v1(2082.68,1948.82) 2082.68,1955.19 R8.2@2129.92,2002.44
TMS: R6.2 U4.A24 | length 134.5
  Top Layer w5: U4.A24@1937.01,1964.57 1937.01,1984.25 1968.5,2015.75 v1(1968.5,2055.12)
  Bottom Layer w5: R6.2@1964.57,2085.12 R6.2@1964.78,2084.23 ; v1(1968.5,2055.12) R6.2@1968.5,2085.11
TOFF: R23.1 U5.7 | length 159.5
  Top Layer w15.75: U5.7@2824.58,1783.25 2824.8,1783.46 2874.02,1783.46 2905.51,1814.96 R23.1@2970.94,1814.96
UGCLK0: U4.B13
UGCLK1: U4.AE13 | length 112.1
  Top Layer w5: 1488.19,917.32 1488.19,960.63 1484.25,964.57 1484.25,1000 U4.AE13@1503.94,1019.68
UGCLK2: U4.AD13 | length 149.9
  Top Layer w7.87: v1(1484.25,1039.37) U4.AD13@1503.94,1059.05
  MidLayer1 w5: 1484.25,917.32 v1(1484.25,1039.37)
VFILT: C117.1 C118.1 R19.2 U5.5 U5.12 | length 544.3
  Top Layer w15.75: R19.2@2492.12,1643.23 2492.12,1688.98 C118.1@2488.18,1692.91 2488.19,1716.54 2504.9,1733.25 U5.12@2592.58,1733.25 ; U5.12@2592.58,1733.25 U5.5@2824.58,1733.25 2904.53,1733.27 2918.31,1719.48 C117.1@2944.88,1719.48
VSET: R18.1 R25.1 U6.5 | length 153
  Top Layer w5: R18.1@1847.95,2358.26 1870.07,2358.26 1875.51,2363.7 1875.51,2462.12 1881.89,2468.5 U6.5@1897.64,2468.5
pads on no net: HDR_B1.93 HDR_B1.95 HDR_B1.MH5 HDR_B1.MH6 HDR_L1.MH5 HDR_L1.MH6 HDR_T1.95 HDR_T1.MH5 HDR_T1.MH6 MH1.MOUNT MH2.MOUNT MH3.MOUNT U1.5 U2.1 U3.A1 U3.A8 U3.B1 U3.B4 U3.C1 U3.D1 U3.E1 U3.F8 U3.G1 U3.G8 U3.H1 U3.H8 U4.A3 U4.A4 U4.A5 U4.A6 U4.A7 U4.AA3 U4.AA5 U4.AA21 U4.AA22 U4.AB13 U4.AB22 U4.AC22 U4.AD1 U4.AD2 U4.AE7 U4.AF7 U4.B3 U4.B5 U4.B6 U4.B7 U4.B14 U4.B18 U4.C25 U4.C26 U4.D5 U4.D14 U4.D22 U4.D25 U4.D26 U4.E5 U4.E9 U4.E16 U4.E22 U4.F5 U4.F6 U4.F7 U4.F22 U4.FID1 U4.G6 U4.G9 U4.G10 U4.G11 U4.G12 U4.G13 U4.G14 U4.G15 U4.G16 U4.G25 U4.H6 U4.H20 U4.J6 U4.K23 U4.N20 U4.N22 U4.N23 U4.N26 U4.P20 U4.R20 U4.T20 U4.T21 U4.U20 U4.U21 U4.U22 U4.V2 U4.V20 U4.V21 U4.V22 U4.W12 U4.W20 U4.W21 U4.W22 U4.Y4 U7.40 U8.40
copper on no net: | length 12274.4
  Top Layer w5: 968.5,1275.59 1051.18,1275.59 1070.87,1295.28 ; 998,1039.37 1051.18,1039.37 1070.87,1059.05 ; 998,1059.05 1031.5,1059.05 ; 1070.87,2027.56 1070.87,2005.91 1090.55,1986.22 1090.55,1944.88 1110.24,1925.2 ; 1082.68,2027.56 1082.68,2011.81 1110.24,1984.25 1110.24,1964.57 ; 1149.61,1964.57 1149.61,1981.91 1149.61,2003.9 ; 1169.29,2003.9 1169.29,1944.88 1188.98,1925.2 ; 1188.98,1964.57 1188.98,1984.25 1192.91,1988.19 1192.91,2027.56 ; 1204.72,2027.56 1204.72,1988.19 1208.66,1984.25 1208.66,1980.32 1208.66,1948.82 1208.66,1944.88 1228.35,1925.2 ; 1216.54,2027.6 1216.54,1996.06 1228.35,1984.25 1228.35,1964.57 ; 1228.35,2027.4 1228.35,2000 1248.03,1980.32 1248.03,1944.88 1267.72,1925.2 ; 1248.03,975.3 1248.03,1000 1267.72,1019.68 ; 1267.72,950.5 1267.72,980.31 ; 1700.79,1925.2 1720.47,1944.88 1720.47,2027.56 ; 1976.38,1728.35 1996.06,1748.03 2031.5,1748.03 2051.18,1767.72 2078.74,1767.72 ; 1976.38,1846.46 1996.06,1866.14 2078.74,1866.14 ; 1976.38,1885.83 1996.06,1905.51 2066.93,1905.51 ; 2015.75,1492.13 2078.74,1492.13 ; 2015.75,1846.46 2035.43,1846.46 2055.12,1826.77 2078.74,1826.77 ; 2015.75,1885.83 2090.55,1885.83
  Top Layer w7.87: v1(1090.55,1157.48) 1110.24,1177.17 ; v1(1129.92,1196.85) 1149.61,1216.54 ; v1(1169.29,1787.4) 1188.98,1767.72 ; v1(1169.29,1826.77) 1188.98,1807.09 ; v1(1169.29,1866.14) 1188.98,1846.46 ; v1(1208.66,1669.29) 1228.35,1649.61 ; v1(1208.66,1708.66) 1228.35,1688.98 ; v1(1208.66,1748.03) 1228.35,1728.35 ; v1(1208.66,1787.4) 1228.35,1767.72 ; v1(1248.03,1787.4) 1267.72,1767.72 ; v1(1326.77,1748.03) 1346.46,1728.35 ; v1(1326.77,1826.77) 1346.46,1807.09 ; v1(1366.14,1748.03) 1385.83,1728.35 ; v1(1405.51,1748.03) 1425.2,1728.35 ; v1(1444.88,1236.22) 1464.57,1255.91 ; v1(1444.88,1748.03) 1464.56,1728.35 ; v1(1484.25,1118.11) 1503.94,1137.79 ; v1(1484.25,1749.02) 1503.94,1728.35 ; 1543.31,1728.35 v1(1562.99,1749.02) ; 1543.31,1846.46 v1(1562.99,1866.14) ; 1582.68,1728.35 v1(1602.36,1748.03) ; 1622.05,1728.35 v1(1641.73,1748.03) ; 1622.05,1807.09 v1(1641.73,1826.77) ; 1779.53,1255.91 v1(1799.21,1236.22) ; 1779.53,1295.28 v1(1799.21,1275.59) ; 1779.53,1334.65 v1(1799.21,1314.96) ; 1779.53,1374.02 v1(1799.21,1354.33) ; 1779.53,1413.39 v1(1799.21,1393.7) ; 1779.53,1452.76 v1(1801.18,1433.07) ; 1779.53,1492.13 v1(1801.18,1511.81) ; 1779.53,1688.98 v1(1799.21,1708.66) ; 1818.9,1177.17 v1(1838.58,1157.48) ; 1818.9,1255.91 v1(1838.58,1236.22) ; 1818.9,1295.28 v1(1838.58,1275.59) ; 1818.9,1334.65 v1(1838.58,1314.96) ; 1818.9,1374.02 v1(1838.58,1354.33) ; 1858.27,1098.42 v1(1877.95,1078.74) ; 1858.27,1137.79 v1(1877.95,1118.11) ; 1858.27,1177.17 v1(1877.95,1157.48) ; 1858.27,1255.91 v1(1877.95,1236.22) ; 1858.27,1295.28 v1(1877.95,1275.59) ; 1858.27,1334.65 v1(1877.95,1314.96) ; 1858.27,1492.13 v1(1877.95,1511.81) ; 1858.27,1807.09 v1(1877.95,1826.77) ; 1858.27,1846.46 v1(1877.95,1866.14) ; 1897.64,1492.13 v1(1917.32,1511.81) ; 1897.64,1610.24 v1(1917.32,1629.92) ; 3149.61,4212.6 3149.61,4330.71
  MidLayer1 w5: 968.5,1157.48 v1(1090.55,1157.48) ; 968.5,1177.17 1110.24,1177.17 v1(1129.92,1196.85) ; 1149.61,1921.26 1149.61,1885.83 v1(1169.29,1866.14) ; v1(1877.95,1078.74) 1897.64,1059.05 1897.64,988.19 1905.51,980.32 1905.51,917.32 ; v1(1877.95,1866.14) 1897.64,1885.83 1897.64,1921.26 ; v1(1917.32,1511.81) 1937.01,1492.13 1968.5,1492.13 1976.38,1500 2078.74,1500 ; v1(1917.32,1629.92) 1937.01,1610.24 2051.18,1610.24 2078.74,1610.24
  MidLayer2 w5: 1307.09,2027.56 1307.09,1846.46 v1(1326.77,1826.77) ; v1(1444.88,1236.22) 1464.57,1216.53 1464.57,1019.68 1464.57,917.32 ; v1(1484.25,1118.11) 1503.94,1098.42 1503.94,917.32 ; v1(1641.73,1826.77) 1661.42,1846.46 1661.42,2027.56 ; v1(1877.95,1118.11) 1897.64,1098.42 2066.93,1098.42 ; v1(1877.95,1157.48) 1897.64,1137.8 2078.74,1137.8 2082.68,1137.8 ; v1(1877.95,1236.22) 1897.64,1216.54 2078.74,1216.54 ; v1(1877.95,1275.59) 1897.64,1255.91 2078.74,1255.91 ; v1(1877.95,1314.96) 1897.64,1295.28 2000,1295.28 ; v1(1877.95,1511.81) 1897.64,1492.13 2078.74,1492.13 ; v1(1877.95,1826.77) 1897.64,1846.46 2074.8,1846.46
  MidLayer3 w5: 968.5,1688.98 1188.97,1688.98 v1(1208.66,1669.29) ; 1078.8,1807 1149.69,1807 v1(1169.29,1787.4) ; 1080.8,1768 1189.26,1768 v1(1208.66,1787.4) ; v1(1169.29,1826.77) 1189,1846.48 1189,1909.6 ; 1228.35,2027.56 1228.34,1807.09 v1(1248.03,1787.4) ; v1(1838.58,1157.48) 1858.27,1137.79 1858.27,1082.68 1858.27,988.19 1874.02,972.44 1874.02,917.32 ; v1(1838.58,1236.22) 1858.27,1216.54 2078.74,1216.54 ; v1(1838.58,1275.59) 1858.27,1255.9 2078.74,1255.91 ; v1(1838.58,1314.96) 1858.27,1295.28 1968.5,1295.28 1992.13,1271.65 2078.74,1271.65 ; v1(1838.58,1354.33) 1858.27,1334.65 2078.74,1334.65
  MidLayer4 w5: 1385.82,2027.56 1385.82,1917.32 1385.83,1763.78 v1(1405.51,1748.03) ; 1425.19,2027.56 1425.19,1937.01 1425.19,1767.72 v1(1444.88,1748.03) ; 1464.57,2027.56 1464.57,1767.72 v1(1484.25,1749.02) ; 1484.25,2027.56 1484.25,1944.88 v1(1562.99,1866.14) ; v1(1562.99,1749.02) 1582.68,1767.72 1582.68,2027.56 ; v1(1602.36,1748.03) 1622.05,1767.72 1622.05,2027.56 ; v1(1641.73,1748.03) 1661.42,1763.78 1661.42,1917.32 1661.42,1937.01 1661.42,2027.56 ; v1(1799.21,1236.22) 1818.9,1216.53 2003.94,1216.53 ; v1(1799.21,1275.59) 1818.9,1255.9 2078.74,1255.9 ; v1(1799.21,1314.96) 1818.9,1295.28 1984.25,1295.28 2003.94,1275.59 2078.74,1275.59 ; v1(1799.21,1354.33) 1814.96,1334.65 1968.5,1334.64 2078.74,1334.64 ; v1(1799.21,1393.7) 1818.9,1374.01 2078.74,1374.01 ; v1(1801.18,1433.07) 1818.9,1413.38 2078.74,1413.39 ; v1(1801.18,1511.81) 1818.9,1531.5 2078.74,1531.5
  other v1: 1618.11,43.31 1456.69,59.06 1771.65,59.06 1556.86,68.68 1679.36,68.68 1531.5,129.92 1704.72,129.92 1556.86,191.17 1679.36,191.17 1618.11,216.54 129.92,4240.16 3106.3,4240.16 68.68,4265.53 191.17,4265.53 3045.05,4265.53 3167.54,4265.53 43.31,4326.77 216.54,4326.77 3019.68,4326.77 3192.91,4326.77 68.68,4388.02 191.17,4388.02 3045.05,4388.02 3167.54,4388.02 129.92,4413.39 3106.3,4413.39

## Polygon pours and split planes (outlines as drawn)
2V5 on Top Layer "2V5-TOP-CAP" (solid, remove dead copper, pour order 1011): 866.14,795.28 1066.93,795.28 1066.93,1011.81 866.14,1011.81
AGND on Top Layer "AGND-TOP" (solid, remove dead copper, pour order 1003): 2377.61,2077.57 2377.61,1677.17 3088.3,1677.17 3088.3,2077.57
GND on Top Layer "GROUND-TOP-LAYER" (solid, remove dead copper, pour order 1012): 19.68,4132.62 298.72,4132.62 298.72,4409.45 2929.63,4409.45 2929.63,4132.62 3208.66,4132.62 3208.66,19.68 1813.48,19.68 1813.48,296.52 1414.86,296.52 1414.86,19.68 19.68,19.68
1V2 on MidLayer1 "1V2-connect-to-L1-C17" (solid, remove dead copper, pour order 1001): 2275.59,1417.32 3165.35,1417.32 3165.35,2200.79 2621.61,2200.79 2621.61,1691.54 2275.59,1691.54
1V2 on MidLayer1 "FPGAPWR-ML1-1V2" (solid, pour order 1000): 1472.13,1854.02 1472.13,2027.56 1574.8,2027.56 1574.8,1850.39 1811.02,1850.39 1901.57,1759.84 1901.57,1519.69 2078.74,1519.69 2078.74,1421.26 1901.57,1421.26 1901.57,1185.04 1811.02,1094.49 1574.8,1094.49 1574.8,917.32 1472.44,917.32 1472.44,1094.49 1236.22,1094.49 1145.67,1185.04 1145.67,1421.26 968.5,1421.26 968.5,1523.62 1145.67,1523.62 1145.67,1767.72 1228.35,1850.39
GND on MidLayer1 "GROUND-MID1-LAYER" (solid, remove dead copper, pour order 1013): 19.68,4132.62 298.72,4132.62 298.72,4409.45 2929.63,4409.45 2929.63,4132.62 3208.66,4132.62 3208.66,19.68 1813.48,19.68 1813.48,296.52 1414.86,296.52 1414.86,19.68 19.68,19.68
2V5 on MidLayer2 "2V5" (solid, remove dead copper, pour order 1002): 2409.45,2322.83 3051.18,2322.83 3051.18,137.8 2409.45,137.8
GND on MidLayer2 "GROUND-MID2-LAYER" (solid, remove dead copper, pour order 1014): 19.68,4132.62 298.72,4132.62 298.72,4409.45 2929.63,4409.45 2929.63,4132.62 3208.66,4132.62 3208.66,19.68 1813.48,19.68 1813.48,296.52 1414.86,296.52 1414.86,19.68 19.68,19.68
GND on MidLayer3 "GROUND-MID3-LAYER" (solid, remove dead copper, pour order 1015): 19.68,4132.62 298.72,4132.62 298.72,4409.45 2929.63,4409.45 2929.63,4132.62 3208.66,4132.62 3208.66,19.68 1813.48,19.68 1813.48,296.52 1414.86,296.52 1414.86,19.68 19.68,19.68
GND on MidLayer4 "GROUND-MID4-LAYER" (solid, remove dead copper, pour order 1016): 19.68,4132.62 298.72,4132.62 298.72,4409.45 2929.63,4409.45 2929.63,4132.62 3208.66,4132.62 3208.66,19.68 1813.48,19.68 1813.48,296.52 1414.86,296.52 1414.86,19.68 19.68,19.68
GND on Bottom Layer "GROUND-BOTTOM-LAYER" (solid, remove dead copper, pour order 1017): 8.88,4109.82 287.92,4109.82 287.92,4386.65 2918.83,4386.65 2918.83,4109.82 3197.86,4109.82 3197.86,-3.12 1802.68,-3.12 1802.68,273.72 1404.06,273.72 1404.06,-3.12 8.88,-3.12
2V5 on Bottom Layer "GAPWR-BL-2V5E" (solid, remove dead copper, pour order 1010): 1417.32,2224.41 1417.32,2027.56 1992,2027.56 1992,2026.17 2072.64,1948.82 2074.09,1947.43 2074.09,1791.34 2669.29,1791.34 2648.77,1811.02 2648.77,2303.15 2546.15,2303.15 2546.15,2224.41
3V3 on Bottom Layer "FPGAPWR-BL-3V3" (solid, pour order 1004): 1500,1405.51 1547.24,1405.51 1590.55,1448.82 1590.55,1496.06 1547.24,1539.37 1500,1539.37 1456.69,1496.06 1456.69,1448.82
1V2 on Bottom Layer "FPGAPWR-BL-1V2" (solid, pour order 1005): 1748.03,1913.39 1940.94,1724.41 1940.94,1224.41 1771.65,1055.12 1275.59,1055.12 1106.3,1224.41 1106.3,1724.41 1299.21,1913.39
2V5 on Bottom Layer "FPGAPWR-BL-2V5C" (solid, remove dead copper, pour order 1008): 2232.28,2100.97 2232.28,851.78 2129.65,791.34 2095.44,791.34 1984.25,871.93 1984.25,2080.82 2095.44,2161.42 2129.65,2161.42
2V5 on Bottom Layer "FPGAPWR-BL-2V5A" (solid, remove dead copper, pour order 1006): 910.66,2224.41 2156.26,2224.41 2216.54,2103.86 2216.54,2063.67 2136.17,1933.07 930.76,1933.07 850.39,2063.67 850.39,2103.86
2V5 on Bottom Layer "FPGAPWR-BL-2V5D" (solid, remove dead copper, pour order 1009): 846.46,2157.25 846.46,850.63 936.06,787.4 965.92,787.4 1062.99,871.7 1062.99,2136.17 965.92,2220.47 936.06,2220.47
2V5 on Bottom Layer "FPGAPWR-BL-2V5B" (solid, remove dead copper, pour order 1007): 2156.09,779.53 906.9,779.53 846.46,875.64 846.46,907.68 927.05,1011.81 2135.94,1011.81 2216.54,907.68 2216.54,875.64
GND on GND-Layer5 (split plane): 1523.62,4436.6 3216.12,4436.6 3216.12,20.1 20.1,20.1 20.1,4436.6 1523.62,4436.6
3V3 on VCC (split plane): 1523.62,4436.6 2701.84,4436.6 2701.84,4061.24 2702.17,4058.67 2703.17,4056.27 2704.74,4054.22 2720.98,4037.98 2721.87,4037.3 2723.04,4036.4 2725.43,4035.41 2728,4035.07 3041.89,4035.07 3106.07,3970.89 3106.07,2319.11 3064.6,2277.64 2921.43,2277.64 2802.3,2396.78 2800.24,2398.36 2797.84,2399.35 2795.28,2399.69 2629.92,2399.69 2627.35,2399.35 2624.96,2398.36 2622.9,2396.78 2617,2390.88 2615.42,2388.82 2614.43,2386.43 2614.09,2383.86 2614.09,2206.87 2429.99,2022.77 2428.41,2020.71 2427.42,2018.32 2427.08,2015.75 2427.08,1590.55 2427.42,1587.98 2428.41,1585.59 2429.99,1583.53 2445.74,1567.78 2447.79,1566.21 2450.19,1565.21 2452.76,1564.88 2582.68,1564.88 2585.25,1565.21 2587.64,1566.21 2589.7,1567.78 2618.29,1596.37 2712.19,1596.37 2725.07,1583.49 2725.07,1440 2725.41,1437.43 2726.4,1435.04 2727.98,1432.98 2732.98,1427.98 2735.04,1426.4 2737.43,1425.41 2740,1425.07 3005.77,1425.07 3045.19,1385.65 3045.19,1287.4 3045.19,1244.09 3045.19,795.45 2948.64,698.9 2838.58,698.9 2836.01,698.57 2833.62,697.57 2831.56,696 2780.38,644.82 2778.8,642.76 2777.81,640.36 2777.47,637.8 2777.47,523.8 2617,363.32 2615.42,361.26 2614.43,358.87 2614.09,356.3 2614.09,20.1 20.1,20.1 20.1,4436.6 1523.62,4436.6
5V0 on VCC (split plane): 3216.12,4436.6 3216.12,20.1 2633.94,20.1 2633.94,352.19 2794.42,512.67 2796,514.72 2796.99,517.12 2797.33,519.68 2797.33,633.68 2842.69,679.05 2952.76,679.05 2955.33,679.39 2957.72,680.38 2959.78,681.96 3062.14,784.32 3063.03,785.48 3063.72,786.37 3064.01,787.08 3064.71,788.77 3065.05,791.34 3065.05,1244.09 3065.05,1287.4 3065.05,1389.76 3064.71,1392.33 3063.72,1394.73 3062.82,1395.89 3062.14,1396.78 3016.9,1442.02 3014.85,1443.6 3012.45,1444.59 3009.88,1444.93 2744.93,1444.93 2744.93,1587.6 2744.59,1590.17 2743.6,1592.56 2742.02,1594.62 2723.32,1613.32 2721.26,1614.9 2718.87,1615.89 2716.3,1616.23 2614.17,1616.23 2611.6,1615.89 2609.21,1614.9 2607.15,1613.32 2578.57,1584.73 2456.87,1584.73 2446.94,1594.66 2446.94,2011.64 2631.04,2195.74 2632.61,2197.79 2633.6,2200.19 2633.94,2202.76 2633.94,2379.75 2634.03,2379.84 2791.16,2379.84 2910.3,2260.7 2911.2,2260.01 2912.36,2259.12 2914.75,2258.13 2917.32,2257.79 3068.72,2257.79 3071.29,2258.13 3073.68,2259.12 3075.74,2260.7 3123.02,2307.98 3124.6,2310.04 3125.59,2312.43 3125.93,2315 3125.93,3975 3125.59,3977.57 3124.6,3979.96 3123.7,3981.13 3123.02,3982.02 3053.02,4052.02 3050.96,4053.6 3048.57,4054.59 3046,4054.93 2732.11,4054.93 2721.69,4065.35 2721.69,4436.6

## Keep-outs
Bottom Layer:
  rectangle: 2643.7,3334.65 2840.55,3417.32
Keep-Out Layer:
  circle w15.75: c2928.82,472.44 r118.11
  circle w15.75: c857.95,472.44 r118.11
  circle w15.75: c306.77,437.01 r118.11
  circle w15.75: c306.77,2507.87 r118.11
  circle w15.75: c857.95,2472.44 r118.11
  circle w15.75: c2928.82,2472.44 r118.11
  region: 3236.22,4456.69 3212.6,4456.69 3212.6,0 3236.22,0
  rectangle: 0,0 23.62,4456.69
  rectangle: 0,0 3236.22,23.62
  region: 0,4456.69 0,4433.07 3236.22,4433.07 3236.22,4456.69
Mechanical 4:
  rectangle: 236.22,4358.27 925.2,4456.69

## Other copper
Top Layer:
  rectangle net GND: 3093.5,1773.6 3142.6,1785.4
  rectangle net GND: 2645.67,2551.18 2740.16,2692.91
  rectangle net 5V0: 2645.67,2251.97 2740.16,2393.7
  region net LX: 2768.7,1716.54 2645.67,1716.54 2645.67,1622.32 2768.7,1622.32
  rectangle net 1V2: 2850.39,2100 3027.56,2195
  rectangle net AGND: 2515.6,1915.2 2523.6,1942.4
  rectangle net 5V0: 2885.41,1479.25 3016.97,1700.34
  rectangle net 5V0: 2807.08,1449.65 2955.14,1558.01
  rectangle net GND: 3011.81,1366.15 3031.49,1405.52
  pour cut-out: 2554.02,3195 2554.02,2865 2194.02,2865 2194.02,3195
  pour cut-out: 995.43,2007.56 2055.43,2007.56 2055.43,947.56 995.43,947.56
MidLayer4:
  rectangle net 5V0: 2625,2240 2755,2370
Bottom Layer:
  rectangle net GND: 2645.67,598.43 2740.16,696.85
  rectangle net 5V0: 2645.67,251.97 2740.16,346.46
  rectangle net GND: 2645.67,2598.43 2740.16,2696.85
  rectangle net 3V3: 1501.97,1405.51 1545.28,1433.07
  region net 3V3: 1590.55,1452.76 1590.55,1492.13 1562.99,1492.13 1562.99,1452.76
  region net 3V3: 1590.55,1450.79 1590.55,1494.09 1562.99,1494.09 1562.99,1450.79
  region net 3V3: 1545.28,1539.37 1501.97,1539.37 1501.97,1511.81 1545.28,1511.81
  region net 3V3: 1456.69,1494.09 1456.69,1450.79 1484.25,1450.79 1484.25,1494.09
  rectangle net 3V3: 2562.99,570.86 2610.24,704.72
  rectangle net 3V3: 2562.99,2570.86 2610.24,2704.72
  rectangle net 5V0: 2645.67,2248.03 2740.16,2346.46
  rectangle net 5V0: 2629.92,2248.03 2740.16,2346.46
  rectangle net LX: 2637.8,1618.11 2799.21,1728.35
  rectangle net 1V2: 2850.39,1972.44 3027.56,2192.91
  region net LX: 2455.79,1920.32 2455.79,2040.32 2305.79,2040.32 2305.79,1920.32
  rectangle net 1V2: 2641.13,1901.74 2787.4,2043.82
  region net GND: 1503.94,1724.41 1503.94,1771.65 1523.62,1791.34 1543.31,1771.65 1543.31,1720.47 1503.94,1720.47
  region net GND: 1775.59,1492.13 1822.83,1492.13 1842.52,1472.44 1822.83,1452.76 1771.65,1452.76 1771.65,1492.13
  region net GND: 1543.31,1220.47 1543.31,1173.23 1523.62,1153.54 1503.94,1173.23 1503.94,1224.41 1543.31,1224.41
  region net GND: 1271.65,1452.76 1224.41,1452.76 1204.72,1472.44 1224.41,1492.13 1275.59,1492.13 1275.59,1452.76
GND-Layer5 (plane layer: these items are gaps in the copper):
  rectangle: 2645.67,2251.97 2740.16,2283.47
  rectangle: 2708.66,2251.97 2740.16,2346.46
  rectangle: 2570.87,661.42 2602.37,724.41
  rectangle: 2708.66,314.96 2740.16,346.46
  rectangle: 2645.67,251.97 2708.66,283.46
  rectangle: 2570.87,2661.42 2602.36,2724.41
  text "GND" at 1645.67,437.01 h60
VCC (plane layer: these items are gaps in the copper):
  lines w19.68: 2624.02,0 2624.02,356.3 2787.4,519.68 2787.4,637.8 2838.58,688.98 2952.76,688.98 3055.12,791.34 3055.12,1244.09 3055.12,1287.4 3055.12,1389.76 3009.88,1435 2740,1435 2735,1440 2735,1587.6 2716.3,1606.3 2614.17,1606.3 2582.68,1574.8 2452.76,1574.8 2437.01,1590.55 2437.01,2015.75 2624.02,2202.76 2624.02,2383.86 2629.92,2389.76 2795.28,2389.76 2917.32,2267.72 3068.72,2267.72 3116,2315 3116,3975 3046,4045 2728,4045 2711.76,4061.24 2711.76,4456.69
  text "5V0" at 2791.34,1826.77 h60
  text "3V3" at 1657.48,437.01 h60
